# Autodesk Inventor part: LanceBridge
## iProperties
Shininess: 64.0
Length Units: 11272
Angle Units: 11279
Time Units: 11290
Mass Units: 11286
Length Display Precision: 3
Angle Display Precision: 2
Compacted: True
Part Number: LanceBridge
Document SubType Name: Sheet Metal
Created: 2005-12
Designer: Administrator
Manufacturer: Standard
Standards Organization: Custom
Density: 0.0
Volumn: 0.0
Area: 0.0
PropertySet Name: Model Information
Control State: 0
Master: False
Checked Out: False
Author: Administrator
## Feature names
1. Extrusion1
2. Extrusion2
3. Extrusion3
4. Plate1
5. Cut1
